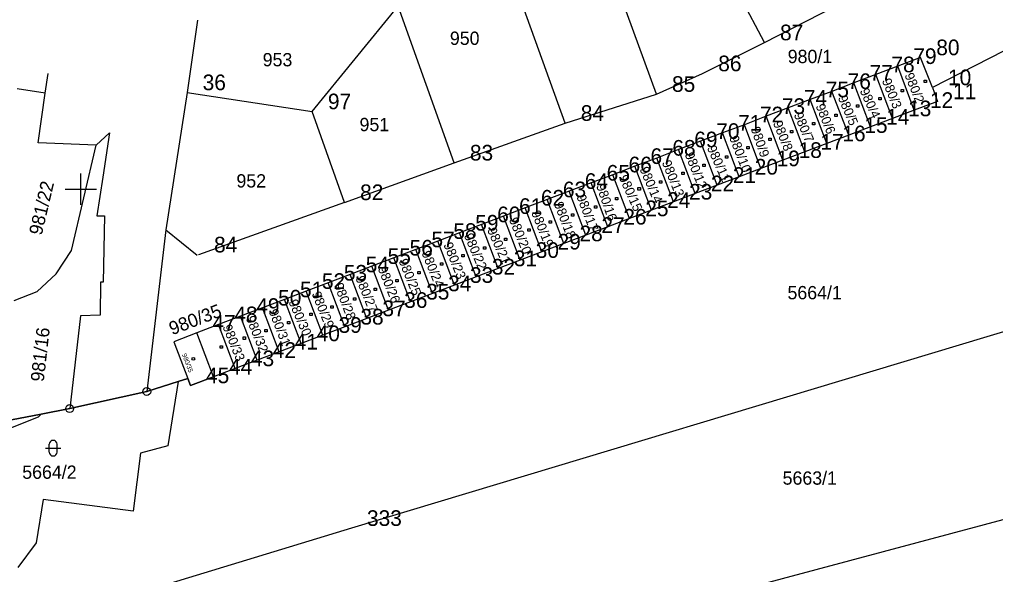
# Model space of a CAD drawing. Extents: x -822293 to -820259, y -1071573 to -1068794.
# Drawn here: x -822107.8 to -821983, y -1070349.2 to -1070278.3 of the extents above; entities that cross this region are included whole.
import ezdxf

# ---------------------------------------------------------------- set-up
doc = ezdxf.new("R2010")
doc.units = 0
for name, color, linetype in [('Vrstva 1', 7, 'Continuous'), ('Vrstva 11', 7, 'Continuous'), ('Vrstva 13', 7, 'Continuous'), ('Vrstva 14', 7, 'Continuous'), ('Vrstva 16', 7, 'Continuous'), ('Vrstva 18', 7, 'Continuous'), ('Vrstva 19', 7, 'Continuous'), ('Vrstva 2', 7, 'Continuous'), ('Vrstva 24', 7, 'Continuous'), ('Vrstva 25', 7, 'Continuous'), ('Vrstva 5', 7, 'Continuous'), ('Vrstva 6', 7, 'Continuous'), ('Vrstva 62', 7, 'Continuous'), ('Vrstva 8', 7, 'Continuous'), ('Vrstva 9', 7, 'Continuous')]:
    doc.layers.add(name, color=color, linetype=linetype)

# ---------------------------------------------------------------- blocks, each defined once
blk = doc.blocks.new('Z402')
at = {"layer": 'Vrstva 2'}
for p, q in [((-10, 10), (20, 10)), ((-10, -20), (-10, 10)), ((20, 10), (20, -20)), ((20, -20), (-10, -20))]:
    blk.add_line(p, q, dxfattribs=at)
blk = doc.blocks.new('02.04')
at = {"layer": 'Vrstva 1'}
for p, q in [((0, -2), (0, 2)), ((-2, 0), (2, 0))]:
    blk.add_line(p, q, dxfattribs=at)

msp = doc.modelspace()

# ---------------------------------------------------------------- linework, layer by layer
at = {"layer": 'Vrstva 1'}
for p, q in [((-822085.068, -1070278.383), (-822086.41, -1070287.63)), ((-822105.47, -1070294.06), (-822104.55, -1070287.71)), ((-822086.41, -1070287.63), (-822089.14, -1070305.18)), ((-822086.41, -1070287.63), (-822070.38, -1070290.07)), ((-822098.02, -1070294.35), (-822096.35, -1070292.76)), ((-822096.35, -1070292.76), (-822097.19, -1070298.46)), ((-822098.02, -1070294.35), (-822105.47, -1070294.06)), ((-822101.2, -1070307.82), (-822098.02, -1070294.35)), ((-822097.19, -1070298.46), (-822097.93, -1070303.38)), ((-822097.93, -1070303.38), (-822096.99, -1070303.37)), ((-822096.99, -1070303.37), (-822097.14, -1070311.88)), ((-822089.14, -1070305.18), (-822091.56, -1070325.85)), ((-822089.14, -1070305.18), (-822085.11, -1070308.43)), ((-822103.14, -1070310.82), (-822101.2, -1070307.82)), ((-822105.57, -1070313.07), (-822103.14, -1070310.82)), ((-822097.49, -1070311.88), (-822097.52, -1070316.1)), ((-822097.14, -1070311.88), (-822097.49, -1070311.88)), ((-822108.54, -1070314.2), (-822105.57, -1070313.07)), ((-822100.06, -1070316.16), (-822101.42, -1070328.03)), ((-822097.52, -1070316.1), (-822100.06, -1070316.16)), ((-822087.55, -1070324.57), (-822088.85, -1070332.78)), ((-822112.98, -1070332.07), (-822105.41, -1070329.08)), ((-822105.41, -1070329.08), (-822105.08, -1070328.74)), ((-822088.85, -1070332.78), (-822092.35, -1070333.74)), ((-822092.35, -1070333.74), (-822093.29, -1070341.15)), ((-822104.81, -1070339.66), (-822105.7, -1070345.18)), ((-822093.29, -1070341.15), (-822104.81, -1070339.66)), ((-822065.38, -1070343.33), (-822203.06, -1070385.13)), ((-822105.7, -1070345.18), (-822108.05, -1070348.33))]:
    msp.add_line(p, q, dxfattribs=at)
at = {"layer": 'Vrstva 13'}
for p, q in [((-822086.31, -1070324.18), (-822087.55, -1070324.57)), ((-822087.55, -1070324.57), (-822086.31, -1070324.18)), ((-822086.31, -1070324.18), (-822085.98, -1070325.09)), ((-822085.98, -1070325.09), (-822083.03, -1070323.98)), ((-822087.55, -1070324.57), (-822091.56, -1070325.85)), ((-822091.56, -1070325.85), (-822087.55, -1070324.57)), ((-822091.56, -1070325.85), (-822101.42, -1070328.03)), ((-822101.42, -1070328.03), (-822091.56, -1070325.85)), ((-822101.42, -1070328.03), (-822105.08, -1070328.74)), ((-822105.08, -1070328.74), (-822101.42, -1070328.03)), ((-822105.08, -1070328.74), (-822110.85, -1070329.85)), ((-822110.85, -1070329.85), (-822105.08, -1070328.74))]:
    msp.add_line(p, q, dxfattribs=at)
at = {"layer": 'Vrstva 14'}
for p, q in [((-822085.98, -1070325.09), (-822086.31, -1070324.18)), ((-822083.03, -1070323.98), (-822085.98, -1070325.09))]:
    msp.add_line(p, q, dxfattribs=at)
at = {"layer": 'Vrstva 2'}
for p, q in [((-822012.52, -1070281.25), (-822024.4, -1070258.32)), ((-822026.35, -1070287.84), (-822036.37, -1070260.18)), ((-822038.02, -1070291.55), (-822048.64, -1070262.04)), ((-822012.52, -1070281.25), (-822001.69, -1070275.66)), ((-822070.38, -1070290.07), (-822059.39, -1070276.59)), ((-822052.21, -1070296.62), (-822059.39, -1070276.59)), ((-821969.39, -1070275.91), (-821991.03, -1070286.99)), ((-822020.43, -1070285.21), (-822012.52, -1070281.25)), ((-821992.53, -1070283.16), (-821995.47, -1070284.28)), ((-821991.03, -1070286.99), (-821992.53, -1070283.16)), ((-821995.47, -1070284.28), (-821998.27, -1070285.34)), ((-821993.34, -1070289.9), (-821995.47, -1070284.28)), ((-822104.55, -1070287.71), (-822104.178, -1070285.196)), ((-822026.35, -1070287.84), (-822020.43, -1070285.21)), ((-821998.27, -1070285.34), (-822001.07, -1070286.41)), ((-821996.14, -1070290.96), (-821998.27, -1070285.34)), ((-822001.07, -1070286.41), (-822003.88, -1070287.48)), ((-821998.94, -1070292.02), (-822001.07, -1070286.41)), ((-822104.55, -1070287.71), (-822108.16, -1070287.16)), ((-822086.41, -1070287.63), (-822070.38, -1070290.07)), ((-822038.02, -1070291.55), (-822026.35, -1070287.84)), ((-822003.88, -1070287.48), (-822006.68, -1070288.54)), ((-822001.74, -1070293.09), (-822003.88, -1070287.48)), ((-821991.03, -1070286.99), (-821990.39, -1070288.78)), ((-822006.68, -1070288.54), (-822009.48, -1070289.6)), ((-822004.55, -1070294.16), (-822006.68, -1070288.54)), ((-821990.39, -1070288.78), (-821993.34, -1070289.9)), ((-822066.26, -1070301.68), (-822070.38, -1070290.07)), ((-821887.79, -1070289.89), (-822065.38, -1070343.33)), ((-822012.29, -1070290.67), (-822015.09, -1070291.74)), ((-822009.48, -1070289.6), (-822012.29, -1070290.67)), ((-822010.15, -1070296.29), (-822012.29, -1070290.67)), ((-822007.35, -1070295.22), (-822009.48, -1070289.6)), ((-821993.34, -1070289.9), (-821996.14, -1070290.96)), ((-822052.21, -1070296.62), (-822038.02, -1070291.55)), ((-822015.09, -1070291.74), (-822017.89, -1070292.8)), ((-822012.96, -1070297.35), (-822015.09, -1070291.74)), ((-821996.14, -1070290.96), (-821998.94, -1070292.02)), ((-822017.89, -1070292.8), (-822020.69, -1070293.86)), ((-822015.76, -1070298.42), (-822017.89, -1070292.8)), ((-822001.74, -1070293.09), (-822004.55, -1070294.16)), ((-821998.94, -1070292.02), (-822001.74, -1070293.09)), ((-822020.69, -1070293.86), (-822023.5, -1070294.93)), ((-822018.56, -1070299.48), (-822020.69, -1070293.86)), ((-822004.55, -1070294.16), (-822007.35, -1070295.22)), ((-822023.5, -1070294.93), (-822026.3, -1070296)), ((-822021.37, -1070300.55), (-822023.5, -1070294.93)), ((-822007.35, -1070295.22), (-822010.15, -1070296.29)), ((-822066.26, -1070301.68), (-822052.21, -1070296.62)), ((-822026.3, -1070296), (-822029.1, -1070297.06)), ((-822024.17, -1070301.61), (-822026.3, -1070296)), ((-822010.15, -1070296.29), (-822012.96, -1070297.35)), ((-822031.91, -1070298.13), (-822034.71, -1070299.19)), ((-822029.1, -1070297.06), (-822031.91, -1070298.13)), ((-822029.77, -1070303.74), (-822031.91, -1070298.13)), ((-822026.97, -1070302.68), (-822029.1, -1070297.06)), ((-822012.96, -1070297.35), (-822015.76, -1070298.42)), ((-822034.71, -1070299.19), (-822037.51, -1070300.25)), ((-822032.58, -1070304.81), (-822034.71, -1070299.19)), ((-822015.76, -1070298.42), (-822018.56, -1070299.48)), ((-822037.51, -1070300.25), (-822040.31, -1070301.32)), ((-822035.38, -1070305.87), (-822037.51, -1070300.25)), ((-822021.37, -1070300.55), (-822024.17, -1070301.61)), ((-822018.56, -1070299.48), (-822021.37, -1070300.55)), ((-822066.26, -1070301.68), (-822084.95, -1070308.37)), ((-822040.31, -1070301.32), (-822043.12, -1070302.38)), ((-822038.18, -1070306.94), (-822040.31, -1070301.32)), ((-822024.17, -1070301.61), (-822026.97, -1070302.68)), ((-822043.12, -1070302.38), (-822045.92, -1070303.45)), ((-822040.99, -1070308), (-822043.12, -1070302.38)), ((-822026.97, -1070302.68), (-822029.77, -1070303.74)), ((-822045.92, -1070303.45), (-822048.72, -1070304.51)), ((-822043.79, -1070309.07), (-822045.92, -1070303.45)), ((-822029.77, -1070303.74), (-822032.58, -1070304.81)), ((-822051.53, -1070305.58), (-822054.33, -1070306.64)), ((-822048.72, -1070304.51), (-822051.53, -1070305.58)), ((-822049.4, -1070311.2), (-822051.53, -1070305.58)), ((-822046.59, -1070310.13), (-822048.72, -1070304.51)), ((-822032.58, -1070304.81), (-822035.38, -1070305.87)), ((-822054.33, -1070306.64), (-822057.13, -1070307.71)), ((-822052.2, -1070312.26), (-822054.33, -1070306.64)), ((-822038.18, -1070306.94), (-822040.99, -1070308)), ((-822035.38, -1070305.87), (-822038.18, -1070306.94)), ((-822057.13, -1070307.71), (-822059.93, -1070308.77)), ((-822055, -1070313.33), (-822057.13, -1070307.71)), ((-822040.99, -1070308), (-822043.79, -1070309.07)), ((-822059.93, -1070308.77), (-822062.74, -1070309.84)), ((-822057.81, -1070314.39), (-822059.93, -1070308.77)), ((-822043.79, -1070309.07), (-822046.59, -1070310.13)), ((-822062.74, -1070309.84), (-822065.54, -1070310.9)), ((-822060.62, -1070315.46), (-822062.74, -1070309.84)), ((-822046.59, -1070310.13), (-822049.4, -1070311.2)), ((-822065.54, -1070310.9), (-822068.34, -1070311.97)), ((-822063.41, -1070316.52), (-822065.54, -1070310.9)), ((-822049.4, -1070311.2), (-822052.2, -1070312.26)), ((-822071.15, -1070313.03), (-822073.95, -1070314.1)), ((-822068.34, -1070311.97), (-822071.15, -1070313.03)), ((-822069.02, -1070318.65), (-822071.15, -1070313.03)), ((-822066.22, -1070317.59), (-822068.34, -1070311.97)), ((-822052.2, -1070312.26), (-822055, -1070313.33)), ((-822073.95, -1070314.1), (-822076.75, -1070315.16)), ((-822071.82, -1070319.72), (-822073.95, -1070314.1)), ((-822057.81, -1070314.39), (-822060.62, -1070315.46)), ((-822055, -1070313.33), (-822057.81, -1070314.39)), ((-822076.75, -1070315.16), (-822079.55, -1070316.23)), ((-822074.63, -1070320.78), (-822076.75, -1070315.16)), ((-822060.62, -1070315.46), (-822063.41, -1070316.52)), ((-822079.55, -1070316.23), (-822082.36, -1070317.29)), ((-822077.43, -1070321.85), (-822079.55, -1070316.23)), ((-822063.41, -1070316.52), (-822066.22, -1070317.59)), ((-822082.36, -1070317.29), (-822085.16, -1070318.36)), ((-822080.23, -1070322.91), (-822082.36, -1070317.29)), ((-822066.22, -1070317.59), (-822069.02, -1070318.65)), ((-822085.16, -1070318.36), (-822088.1, -1070319.48)), ((-822083.03, -1070323.98), (-822085.16, -1070318.36)), ((-822069.02, -1070318.65), (-822071.82, -1070319.72)), ((-822088.1, -1070319.48), (-822086.31, -1070324.18)), ((-822071.82, -1070319.72), (-822074.63, -1070320.78)), ((-822077.43, -1070321.85), (-822080.23, -1070322.91)), ((-822074.63, -1070320.78), (-822077.43, -1070321.85)), ((-822080.23, -1070322.91), (-822083.03, -1070323.98)), ((-822083.03, -1070323.98), (-822085.98, -1070325.09)), ((-821941.06, -1070331.3), (-822060.87, -1070363.29)), ((-822065.38, -1070343.33), (-822203.06, -1070385.13))]:
    msp.add_line(p, q, dxfattribs=at)
at = {"layer": 'Vrstva 24'}
for centre, radius in [((-822091.56, -1070325.85), 0.5), ((-822091.56, -1070325.85), 0.5), ((-822091.56, -1070325.85), 0.0327), ((-822091.56, -1070325.85), 0.0327), ((-822101.42, -1070328.03), 0.5), ((-822101.42, -1070328.03), 0.5), ((-822101.42, -1070328.03), 0.0327), ((-822101.42, -1070328.03), 0.0327)]:
    msp.add_circle(centre, radius, dxfattribs=at)
at = {"layer": 'Vrstva 25'}
for p, q in [((-822104.54, -1070333.09), (-822102.54, -1070333.09)), ((-822104.04, -1070333.59), (-822104.04, -1070332.59)), ((-822103.04, -1070333.59), (-822103.04, -1070332.59))]:
    msp.add_line(p, q, dxfattribs=at)
msp.add_circle((-822085.6, -1070321.68), 0.175, dxfattribs=at)
for centre, start, end in [((-822103.54, -1070332.59), 0, 180), ((-822103.54, -1070333.59), 180, 0)]:
    msp.add_arc(centre, 0.5, start, end, dxfattribs=at)
at = {"layer": 'Vrstva 8'}
for p, q in [((-822012.52, -1070281.25), (-822012.52, -1070281.25)), ((-821992.53, -1070283.16), (-821992.53, -1070283.16)), ((-821995.47, -1070284.28), (-821995.47, -1070284.28)), ((-822020.43, -1070285.21), (-822020.43, -1070285.21)), ((-821998.27, -1070285.34), (-821998.27, -1070285.34)), ((-822001.07, -1070286.41), (-822001.07, -1070286.41)), ((-822086.41, -1070287.63), (-822086.41, -1070287.63)), ((-822026.35, -1070287.84), (-822026.35, -1070287.84)), ((-822003.88, -1070287.48), (-822003.88, -1070287.48)), ((-821991.03, -1070286.99), (-821991.03, -1070286.99)), ((-822006.68, -1070288.54), (-822006.68, -1070288.54)), ((-821990.39, -1070288.78), (-821990.39, -1070288.78)), ((-822070.38, -1070290.07), (-822070.38, -1070290.07)), ((-822012.29, -1070290.67), (-822012.29, -1070290.67)), ((-822009.48, -1070289.6), (-822009.48, -1070289.6)), ((-821993.34, -1070289.9), (-821993.34, -1070289.9)), ((-822038.02, -1070291.55), (-822038.02, -1070291.55)), ((-822015.09, -1070291.74), (-822015.09, -1070291.74)), ((-821996.14, -1070290.96), (-821996.14, -1070290.96)), ((-822017.89, -1070292.8), (-822017.89, -1070292.8)), ((-822001.74, -1070293.09), (-822001.74, -1070293.09)), ((-821998.94, -1070292.02), (-821998.94, -1070292.02)), ((-822020.69, -1070293.86), (-822020.69, -1070293.86)), ((-822004.55, -1070294.16), (-822004.55, -1070294.16)), ((-822023.5, -1070294.93), (-822023.5, -1070294.93)), ((-822007.35, -1070295.22), (-822007.35, -1070295.22)), ((-822052.21, -1070296.62), (-822052.21, -1070296.62)), ((-822026.3, -1070296), (-822026.3, -1070296)), ((-822010.15, -1070296.29), (-822010.15, -1070296.29)), ((-822031.91, -1070298.13), (-822031.91, -1070298.13)), ((-822029.1, -1070297.06), (-822029.1, -1070297.06)), ((-822012.96, -1070297.35), (-822012.96, -1070297.35)), ((-822034.71, -1070299.19), (-822034.71, -1070299.19)), ((-822015.76, -1070298.42), (-822015.76, -1070298.42)), ((-822037.51, -1070300.25), (-822037.51, -1070300.25)), ((-822021.37, -1070300.55), (-822021.37, -1070300.55)), ((-822018.56, -1070299.48), (-822018.56, -1070299.48)), ((-822066.26, -1070301.68), (-822066.26, -1070301.68)), ((-822040.31, -1070301.32), (-822040.31, -1070301.32)), ((-822024.17, -1070301.61), (-822024.17, -1070301.61)), ((-822043.12, -1070302.38), (-822043.12, -1070302.38)), ((-822026.97, -1070302.68), (-822026.97, -1070302.68)), ((-822045.92, -1070303.45), (-822045.92, -1070303.45)), ((-822029.77, -1070303.74), (-822029.77, -1070303.74)), ((-822051.53, -1070305.58), (-822051.53, -1070305.58)), ((-822048.72, -1070304.51), (-822048.72, -1070304.51)), ((-822032.58, -1070304.81), (-822032.58, -1070304.81)), ((-822054.33, -1070306.64), (-822054.33, -1070306.64)), ((-822038.18, -1070306.94), (-822038.18, -1070306.94)), ((-822035.38, -1070305.87), (-822035.38, -1070305.87)), ((-822057.13, -1070307.71), (-822057.13, -1070307.71)), ((-822040.99, -1070308), (-822040.99, -1070308)), ((-822084.95, -1070308.37), (-822084.95, -1070308.37)), ((-822059.93, -1070308.77), (-822059.93, -1070308.77)), ((-822043.79, -1070309.07), (-822043.79, -1070309.07)), ((-822062.74, -1070309.84), (-822062.74, -1070309.84)), ((-822046.59, -1070310.13), (-822046.59, -1070310.13)), ((-822065.54, -1070310.9), (-822065.54, -1070310.9)), ((-822049.4, -1070311.2), (-822049.4, -1070311.2)), ((-822071.15, -1070313.03), (-822071.15, -1070313.03)), ((-822068.34, -1070311.97), (-822068.34, -1070311.97)), ((-822052.2, -1070312.26), (-822052.2, -1070312.26)), ((-822073.95, -1070314.1), (-822073.95, -1070314.1)), ((-822057.81, -1070314.39), (-822057.81, -1070314.39)), ((-822055, -1070313.33), (-822055, -1070313.33)), ((-822076.75, -1070315.16), (-822076.75, -1070315.16)), ((-822060.62, -1070315.46), (-822060.62, -1070315.46)), ((-822079.55, -1070316.23), (-822079.55, -1070316.23)), ((-822063.41, -1070316.52), (-822063.41, -1070316.52)), ((-822082.36, -1070317.29), (-822082.36, -1070317.29)), ((-822066.22, -1070317.59), (-822066.22, -1070317.59)), ((-822085.16, -1070318.36), (-822085.16, -1070318.36)), ((-822069.02, -1070318.65), (-822069.02, -1070318.65)), ((-822071.82, -1070319.72), (-822071.82, -1070319.72)), ((-822077.43, -1070321.85), (-822077.43, -1070321.85)), ((-822074.63, -1070320.78), (-822074.63, -1070320.78)), ((-822080.23, -1070322.91), (-822080.23, -1070322.91)), ((-822083.03, -1070323.98), (-822083.03, -1070323.98)), ((-822085.98, -1070325.09), (-822085.98, -1070325.09)), ((-822065.38, -1070343.33), (-822065.38, -1070343.33))]:
    msp.add_line(p, q, dxfattribs=at)

# ---------------------------------------------------------------- block references
at = {"layer": 'Vrstva 11', "xscale": 0.01, "yscale": 0.01}
for p in [(-821991.96, -1070286.15), (-821994.93, -1070287.35), (-822000.66, -1070289.3), (-821997.78, -1070288.37), (-822003.41, -1070290.5), (-822006.26, -1070291.57), (-822009.1, -1070292.59), (-822011.85, -1070293.56), (-822014.69, -1070294.63), (-822020.3, -1070296.87), (-822017.42, -1070295.81), (-822023.01, -1070297.89), (-822025.85, -1070299.01), (-822028.6, -1070299.89), (-822031.49, -1070301.14), (-822037.13, -1070303.23), (-822034.16, -1070302.2), (-822039.95, -1070304.13), (-822042.7, -1070305.15), (-822045.68, -1070306.35), (-822048.38, -1070307.46), (-822053.89, -1070309.51), (-822051.14, -1070308.44), (-822056.78, -1070310.62), (-822059.57, -1070311.64), (-822062.35, -1070312.72), (-822065.01, -1070313.97), (-822067.9, -1070314.99), (-822073.45, -1070316.99), (-822070.61, -1070315.92), (-822076.34, -1070318.01), (-822079.13, -1070318.98), (-822082.06, -1070320.1)]:
    msp.add_blockref('Z402', p, dxfattribs=at)
at = {"layer": 'Vrstva 62'}
msp.add_blockref('02.04', (-822100, -1070300), dxfattribs=at)

# ---------------------------------------------------------------- texts
at = {"layer": 'Vrstva 16'}
msp.add_text('980/35', height=1.7, rotation=20.85111, dxfattribs=at).set_placement((-822088.317, -1070318.669))
at = {"layer": 'Vrstva 18'}
for s, rotation, p in [('981/22', 76.71708, (-822105.003, -1070305.958)), ('981/16', 83.46456, (-822104.748, -1070324.667))]:
    msp.add_text(s, height=1.7, rotation=rotation, dxfattribs=at).set_placement(p)
msp.add_text('5664/2', height=1.7, dxfattribs=at).set_placement((-822107.494, -1070337.01))
at = {"layer": 'Vrstva 19'}
msp.add_text('980/35', height=0.6, rotation=290.70207, dxfattribs=at).set_placement((-822087.066, -1070321.108))
at = {"layer": 'Vrstva 5'}
for s, p in [('950', (-822052.773, -1070281.54)), ('953', (-822076.726, -1070284.28)), ('980/1', (-822009.543, -1070283.87)), ('951', (-822064.333, -1070292.57)), ('952', (-822080.086, -1070299.77)), ('5664/1', (-822009.573, -1070314.06)), ('5663/1', (-822010.193, -1070337.76))]:
    msp.add_text(s, height=1.7, dxfattribs=at).set_placement(p)
at = {"layer": 'Vrstva 6'}
for s, rotation, p in [('980/2', 292, (-821994.62, -1070285.39)), ('980/3', 292, (-821997.51, -1070286.1)), ('980/5', 293, (-822003.15, -1070288.28)), ('980/4', 294, (-822000.35, -1070287.39)), ('980/6', 292, (-822005.99, -1070289.34)), ('980/7', 293, (-822008.79, -1070290.46)), ('980/8', 292, (-822011.45, -1070291.52)), ('980/10', 291, (-822017.05, -1070293.39)), ('980/9', 289, (-822014.29, -1070292.23)), ('980/11', 294, (-822019.9, -1070294.7)), ('980/12', 292, (-822022.74, -1070295.54)), ('980/13', 292, (-822025.67, -1070296.56)), ('980/15', 294, (-822031.18, -1070298.47)), ('980/14', 293, (-822028.52, -1070297.41)), ('980/16', 289, (-822034.07, -1070299.54)), ('980/17', 291, (-822036.6, -1070300.92)), ('980/18', 291, (-822039.48, -1070301.85)), ('980/19', 292, (-822042.39, -1070302.98)), ('980/20', 292, (-822045.23, -1070303.87)), ('980/22', 293, (-822051, -1070305.91)), ('980/21', 294, (-822048.03, -1070305.2)), ('980/23', 292, (-822053.62, -1070307.06)), ('980/24', 292, (-822056.42, -1070308.13)), ('980/25', 292, (-822059.35, -1070309.15)), ('980/26', 292, (-822062.02, -1070310.13)), ('980/27', 292, (-822064.88, -1070311.34)), ('980/29', 292, (-822070.48, -1070313.34)), ('980/28', 291, (-822067.63, -1070312.23)), ('980/30', 293, (-822073.45, -1070314.37)), ('980/31', 291, (-822075.98, -1070315.56)), ('980/32', 292, (-822078.91, -1070316.45)), ('980/33', 292, (-822081.89, -1070317.56))]:
    msp.add_text(s, height=1.2, rotation=rotation, dxfattribs=at).set_placement(p)
at = {"layer": 'Vrstva 9'}
for s, p in [('87', (-822010.52, -1070280.95)), ('79', (-821993.47, -1070283.98)), ('80', (-821990.53, -1070282.86)), ('86', (-822018.43, -1070284.91)), ('78', (-821996.27, -1070285.04)), ('77', (-821999.07, -1070286.11)), ('36', (-822084.41, -1070287.33)), ('85', (-822024.35, -1070287.54)), ('76', (-822001.88, -1070287.18)), ('10', (-821989.03, -1070286.69)), ('75', (-822004.68, -1070288.24)), ('11', (-821988.39, -1070288.48)), ('97', (-822068.38, -1070289.77)), ('74', (-822007.48, -1070289.3)), ('12', (-821991.34, -1070289.6)), ('84', (-822036.02, -1070291.25)), ('72', (-822013.09, -1070291.44)), ('73', (-822010.29, -1070290.37)), ('13', (-821994.14, -1070290.66)), ('71', (-822015.89, -1070292.5)), ('14', (-821996.94, -1070291.72)), ('70', (-822018.69, -1070293.56)), ('16', (-822002.55, -1070293.86)), ('15', (-821999.74, -1070292.79)), ('69', (-822021.5, -1070294.63)), ('17', (-822005.35, -1070294.92)), ('83', (-822050.21, -1070296.32)), ('68', (-822024.3, -1070295.7)), ('18', (-822008.15, -1070295.99)), ('67', (-822027.1, -1070296.76)), ('19', (-822010.96, -1070297.05)), ('65', (-822032.71, -1070298.89)), ('66', (-822029.91, -1070297.83)), ('20', (-822013.76, -1070298.12)), ('64', (-822035.51, -1070299.95)), ('21', (-822016.56, -1070299.18)), ('82', (-822064.26, -1070301.38)), ('63', (-822038.31, -1070301.02)), ('23', (-822022.17, -1070301.31)), ('22', (-822019.37, -1070300.25)), ('62', (-822041.12, -1070302.08)), ('24', (-822024.97, -1070302.38)), ('61', (-822043.92, -1070303.15)), ('25', (-822027.77, -1070303.44)), ('60', (-822046.72, -1070304.21)), ('26', (-822030.58, -1070304.51)), ('58', (-822052.33, -1070306.34)), ('59', (-822049.53, -1070305.28)), ('27', (-822033.38, -1070305.57)), ('57', (-822055.13, -1070307.41)), ('29', (-822038.99, -1070307.7)), ('28', (-822036.18, -1070306.64)), ('84', (-822082.95, -1070308.07)), ('56', (-822057.93, -1070308.47)), ('30', (-822041.79, -1070308.77)), ('55', (-822060.74, -1070309.54)), ('31', (-822044.59, -1070309.83)), ('54', (-822063.54, -1070310.6)), ('32', (-822047.4, -1070310.9)), ('53', (-822066.34, -1070311.67)), ('33', (-822050.2, -1070311.96)), ('51', (-822071.95, -1070313.8)), ('52', (-822069.15, -1070312.73)), ('34', (-822053, -1070313.03)), ('50', (-822074.75, -1070314.86)), ('36', (-822058.62, -1070315.16)), ('35', (-822055.81, -1070314.09)), ('49', (-822077.55, -1070315.93)), ('37', (-822061.41, -1070316.22)), ('48', (-822080.36, -1070316.99)), ('38', (-822064.22, -1070317.29)), ('47', (-822083.16, -1070318.06)), ('39', (-822067.02, -1070318.35)), ('40', (-822069.82, -1070319.42)), ('41', (-822072.63, -1070320.48)), ('43', (-822078.23, -1070322.61)), ('42', (-822075.43, -1070321.55)), ('44', (-822081.03, -1070323.68)), ('45', (-822083.98, -1070324.79)), ('333', (-822063.38, -1070343.03))]:
    msp.add_text(s, height=2, dxfattribs=at).set_placement(p)

doc.saveas('drawing.dxf')
